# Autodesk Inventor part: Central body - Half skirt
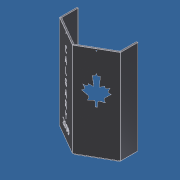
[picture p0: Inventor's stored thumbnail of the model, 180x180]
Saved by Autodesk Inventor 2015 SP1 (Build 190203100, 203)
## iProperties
Category: Mechanical Engineering Drawing and Design - CADD
Manager: Fábio Ricardo de Oliveira Souza
Company: SENAI - Serviço Nacional de Aprendizagem Industrial
Created: 2011-06
Part Number: Central body - Half skirt
Material: Steel
Description: Stainless Steel (DIN- X6NiCrTi18-10)
Document SubType Name: Sheet Metal
Designer: Guilherme Augusto Franco de Souza
Engineer: George Geraldo de Oliveia Silva
Authority: Fábio Ricardo de Oliveira Soza
Density: 7.85 g/cm^3
Sheet Metal Rule: Default_mm
Flat Pattern Width: 74.1468 cm
Flat Pattern Length: 67.5716 cm
Flat Pattern Area: 5010.21 cm^2
Sheet Metal Width: 741,468 mm
Sheet Metal Length: 675,716 mm
Sheet Metal Area: 501021,249 mm^2
Appearance: Machined 02
Subject: WorldSkill 2011 - London, England
Author: Guilherme Augusto Franco de Souza
Revision Number: 00
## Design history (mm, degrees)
sketch "Sketch1"
  geometry: L1 (0, -242.487)-(-210, -121.244); L2 (-210, -121.244)-(-210, 121.244); L3 (-210, 121.244)-(0, 242.487); L4 (0, 242.487)-(210, 121.244); L5 (210, 121.244)-(210, -121.244); L6 (210, -121.244)-(0, -242.487); 2 further points
  constraints: 12 end point, 1 coincident, 1 vertical alignment, 13 other
  dimensions: "d0" = 420 distance between parallel lines of L5 L2
extrude_surface "ExtrusionSrf1" sketch "Sketch1" dims "d1" = 648, "d2" = 0
feature "Trim1"
fillet "Fillet1" dims "d3" = 1.5 (computed from Thickness)
thicken "Thicken1" dims "d4" = 1.2 (= Thickness)
node "Flange1"
node "Flange2"
node "Flange4"
sketch "Sketch6"
  geometry: L1 (0.346, 645.6)-(240.409, 645.6) reference; 2 further points
  constraints: 1 vertical alignment
  dimensions: "d45" = 13 distance from line of L1 point (120.378, 632.6)
hole "Hole1" sketch "Sketch6" at (120.378, 632.6) diameter "d46" = 6.6; stored, may be unused: countersink angle "d50" = 90 deg, drill point angle "d52" = 118 deg; dims "d47" = 6, "d48" = 18, "d49" = 4.8, "d51" = 1.2 (= Thickness)
mirror "Mirror1"
sketch "Sketch7"
  geometry: L1 (6.755, -12.4)-(234, -12.4) reference; 2 further points
  constraints: 1 vertical alignment, 1 other
  dimensions: "d54" = 70 distance from line of L1 point (120.378, 57.6)
emboss "Emboss1" sketch "Sketch7" dims "d6" = 0.6 (= BendReliefDepth), "d55" = 1.2 (= Thickness), "d56" = 0
sketch "Sketch8"
  geometry: L1 (120.378, 297.6)-(126.378, 297.6); L2 (126.378, 297.6)-(126.378, 337.6); L3 (126.378, 337.6)-(165.378, 330.723); L4 (165.378, 330.723)-(156.696, 354.575); L5 (156.696, 354.575)-(195.378, 387.032); L6 (195.378, 387.032)-(175.594, 394.233); L7 (175.594, 394.233)-(189.086, 423.167); L8 (189.086, 423.167)-(160.152, 409.675); L9 (160.152, 409.675)-(161.987, 430.648); L10 (161.987, 430.648)-(136.003, 418.532); L11 (120.378, -144.039)-(120.378, 777.437) reference; L12 (189.086, 423.167)-(120.378, 354.459); L13 (175.594, 394.233)-(160.152, 409.675); L14 (136.003, 418.532)-(136.003, 433.532); L15 (136.003, 433.532)-(140.378, 483.532); L16 (140.378, 483.532)-(127.657, 477.6); L17 (127.657, 477.6)-(120.378, 497.6); L18 (120.378, 497.6)-(120.378, 297.6); L19 (6.755, -12.4)-(234, -12.4) reference; L20 (75.378, 330.723)-(84.059, 354.575); L21 (120.378, 297.6)-(114.378, 297.6); L22 (84.059, 354.575)-(45.378, 387.032); L23 (114.378, 297.6)-(114.378, 337.6); L24 (45.378, 387.032)-(65.161, 394.233); L25 (65.161, 394.233)-(80.603, 409.675); L26 (65.161, 394.233)-(51.669, 423.167); L27 (51.669, 423.167)-(120.378, 354.459); L28 (114.378, 337.6)-(75.378, 330.723); L29 (80.603, 409.675)-(78.768, 430.648); L30 (78.768, 430.648)-(104.752, 418.532); L31 (104.752, 418.532)-(104.752, 433.532); L32 (104.752, 433.532)-(100.378, 483.532); L33 (100.378, 483.532)-(113.098, 477.6); L34 (113.098, 477.6)-(120.378, 497.6); L35 (51.669, 423.167)-(80.603, 409.675); 1 further point
  constraints: 66 end point, 13 symmetric about line, 3 point on line, 2 equal length, 2 parallel, 1 collinear, 1 horizontal, 1 perpendicular, 1 vertical, 1 other
  dimensions: "d57" = 80 deg angle of L2 L3; "d58" = 60 deg angle of L3 L4; "d64" = 20 deg angle of L11 L17; "d65" = 20 vertical distance of L16.end L17.end; "d66" = 50 vertical distance of L14.end L15.end; "d67" = 15 distance of L10.end L14.end; "d68" = 60 deg angle of L16 L15; "d69" = 85 deg angle of L17 L16; "d70" = 40 deg angle of L8 L7; "d71" = 60 deg angle of L5 L6; "d72" = 60 deg angle of L10 L9; "d73" = 85 deg angle of L7 L6; "d74" = 30 distance from line of L7.end L13; "d75" = 45 deg angle of L18 L12; "d76" = 30 distance from line of L12 L5.end; "d77" = 20 distance from line of L11 L15.end; "d78" = 200 distance of L17.end L1.start; "d79" = 6 distance between parallel lines of L18 L2; "d80" = 40 distance of L1.end L2.end; "d81" = 75 distance from line of L18 L5.end; "d82" = 310 distance between parallel lines of L19 L1; "d83" = 45 distance from line of L18 L3.end
cut "Cut1" sketch "Sketch8" dims "d84" = 1.2 (= Thickness), "d85" = 0
feature "Corner Round1" dims "d86" = 10
node "Face1"
  sketch "Sketch9"
    geometry: L1 (133.918, 100.961)-(136.918, 100.961); L2 (136.918, 100.961)-(136.918, 52.552); L3 (136.918, 52.552)-(133.918, 52.552); L4 (133.918, 52.552)-(133.918, 100.961); L5 (103.902, 101.827)-(106.902, 101.827); L6 (106.902, 101.827)-(106.902, 53.418); L7 (106.902, 53.418)-(103.902, 53.418); L8 (103.902, 53.418)-(103.902, 101.827); L9 (112.679, 225.558)-(112.679, 210.517) reference; L10 (103.902, 219.538)-(138.933, 219.538); L11 (138.933, 219.538)-(138.933, 216.538); L12 (138.933, 216.538)-(103.902, 216.538); L13 (103.902, 216.538)-(103.902, 219.538); L14 (126.18, 271.741)-(119.989, 290.574) reference; L15 (119.989, 290.574)-(113.83, 271.741) reference; L16 (122.616, 282.582)-(123.553, 279.732); L17 (123.553, 279.732)-(145.154, 286.834); L18 (145.154, 286.834)-(144.217, 289.684); L19 (144.217, 289.684)-(122.616, 282.582); L20 (117.375, 282.583)-(116.443, 279.732); L21 (116.443, 279.732)-(99.552, 285.255); L22 (99.552, 285.255)-(100.484, 288.107); L23 (100.484, 288.107)-(117.375, 282.583); L24 (126.18, 469.318)-(119.989, 488.151) reference; L25 (119.989, 488.151)-(113.83, 469.318) reference; L26 (122.616, 480.159)-(123.553, 477.309); L27 (123.553, 477.309)-(139.447, 482.534); L28 (139.447, 482.534)-(138.51, 485.384); L29 (138.51, 485.384)-(122.616, 480.159); L30 (117.375, 480.16)-(116.443, 477.309); L31 (116.443, 477.309)-(102.535, 481.857); L32 (102.535, 481.857)-(103.467, 484.708); L33 (103.467, 484.708)-(117.375, 480.16); L34 (150.779, 86.944)-(182.005, 86.944); L35 (182.005, 86.944)-(182.005, 83.944); L36 (182.005, 83.944)-(150.779, 83.944); L37 (150.779, 83.944)-(150.779, 86.944); 13 further points
    constraints: 64 end point, 16 parallel, 13 midpoint, 8 perpendicular, 7 equal length, 4 collinear, 4 horizontal, 2 horizontal alignment, 2 vertical alignment
    dimensions: "d87" = 3 distance between parallel lines of L8 L6
body "Solid1"
body "Srf1"
sketch "Sketch2"
  geometry: L1 through (0, 60.189) direction (0, -1); L2 through (6, 0) direction (1, 0); L3 (12, 0)-(12, 120.378); L4 (12, 120.378)-(0, 120.378)
  constraints: 6 end point, 1 horizontal, 1 perpendicular, 1 vertical
face "Plate1" dims "d5" = 1.2 (= BendReliefWidth), "d6" = 0.6 (= BendReliefDepth), "d7" = 2.4 (= MinimumRemnant), "d8" = 1.2 (= BendRadius), "d9" = 12, "d10" = 90 deg, "d11" = 1.2 (= BendRadius), "d12" = 4.8 (= CornerReliefSize), "d13" = 0.6 (= 0.5 x GapSize), "d14" = 1.2 (= JacobiRadiusSize), "SeamGap" = 0.01, "Thickness" = 1.2 (derived)
bend "Bend1" dims "d5" = 1.2 (= BendReliefWidth), "d6" = 0.6 (= BendReliefDepth), "d7" = 2.4 (= MinimumRemnant), "d8" = 1.2 (= BendRadius), "d9" = 12, "d10" = 90 deg, "d11" = 1.2 (= BendRadius), "SeamGap" = 0.01, "Thickness" = 1.2 (derived)
feature "Corner1" dims "d9" = 12, "d10" = 90 deg, "d12" = 4.8 (= CornerReliefSize), "d13" = 0.6 (= 0.5 x GapSize), "d14" = 1.2 (= JacobiRadiusSize)
sketch "Sketch3"
  geometry: L1 through (-104.25, 60.189) direction (0.866, -0.5); L2 through (2.5, 4.33) direction (0.5, 0.866); L3 (5, 8.66)-(-203.5, 129.038); L4 (-203.5, 129.038)-(-208.5, 120.378)
  constraints: 6 end point, 1 perpendicular, 2 other
face "Plate2" dims "d15" = 1.2 (= BendReliefWidth), "d16" = 0.6 (= BendReliefDepth), "d17" = 2.4 (= MinimumRemnant), "d18" = 1.2 (= BendRadius), "d19" = 10, "d20" = 90 deg, "d21" = 0.3 (= 0.25 x BendRadius), "d22" = 4.8 (= CornerReliefSize), "d23" = 0.6 (= 0.5 x GapSize), "d24" = 1.2 (= JacobiRadiusSize), "SeamGap" = 0.01, "Thickness" = 1.2 (derived)
bend "Bend2" dims "d15" = 1.2 (= BendReliefWidth), "d16" = 0.6 (= BendReliefDepth), "d17" = 2.4 (= MinimumRemnant), "d18" = 1.2 (= BendRadius), "d19" = 10, "d20" = 90 deg, "d21" = 0.3 (= 0.25 x BendRadius), "SeamGap" = 0.01, "Thickness" = 1.2 (derived)
feature "Corner2" dims "d19" = 10, "d20" = 90 deg, "d22" = 4.8 (= CornerReliefSize), "d23" = 0.6 (= 0.5 x GapSize), "d24" = 1.2 (= JacobiRadiusSize)
sketch "Sketch5"
  geometry: L1 through (56.984, 0) direction (-1, 2.8e-31); L2 through (0, -5.6) direction (7.64e-30, -1); L3 (0, -11.2)-(113.969, -11.2); L4 (113.969, -11.2)-(113.969, 0)
  constraints: 6 end point, 1 horizontal, 1 perpendicular, 1 vertical
face "Plate4" dims "d35" = 1.2 (= BendReliefWidth), "d36" = 0.6 (= BendReliefDepth), "d37" = 2.4 (= MinimumRemnant), "d38" = 1.2 (= BendRadius), "d39" = 11.2 (computed from Thickness), "d40" = 90 deg, "d41" = 0.3 (derived), "d42" = 4.8 (= CornerReliefSize), "d43" = 1.2 (= GapSize), "d44" = 1.2 (= JacobiRadiusSize), "SeamGap" = 0.01, "Thickness" = 1.2 (derived)
bend "Bend4" dims "d35" = 1.2 (= BendReliefWidth), "d36" = 0.6 (= BendReliefDepth), "d37" = 2.4 (= MinimumRemnant), "d38" = 1.2 (= BendRadius), "d39" = 11.2 (computed from Thickness), "d40" = 90 deg, "d41" = 0.3 (derived), "SeamGap" = 0.01, "Thickness" = 1.2 (derived)
feature "Corner4" dims "d39" = 11.2 (computed from Thickness), "d40" = 90 deg, "d42" = 4.8 (= CornerReliefSize), "d43" = 1.2 (= GapSize), "d44" = 1.2 (= JacobiRadiusSize)
face "Plate5" dims "d88" = 1.2 (= BendRadius), "d89" = 1.2 (= BendReliefWidth), "d91" = 2.4 (= MinimumRemnant), "Thickness" = 1.2 (derived)
bend "Bend5" dims "d88" = 1.2 (= BendRadius), "d89" = 1.2 (= BendReliefWidth), "d90" = 0.6 (= BendReliefDepth), "d91" = 2.4 (= MinimumRemnant), "d92" = 1.2 (= BendRadius), "SeamGap" = 0.01, "Thickness" = 1.2 (derived)
feature "Definition1"
other parameters: "BendRadius" = 1.2 (= Thickness), "BendReliefWidth" = 1.2 (= Thickness), "BendReliefDepth" = 0.6 (= 0.5 x Thickness), "CornerReliefSize" = 4.8 (= 4 x Thickness), "MinimumRemnant" = 2.4 (= 2 x Thickness), "TransitionRadius" = 1.2 (= BendRadius), "JacobiRadiusSize" = 1.2 (= BendRadius), "GapSize" = 1.2 (= Thickness), "BendRadius" = 1.2, "BendReliefDepth" = 0.6, "BendReliefWidth" = 1.2, "CornerReliefSize" = 4.8, "GapSize" = 1.2, "JacobiRadiusSize" = 1.2, "MinimumRemnant" = 2.4, "Thickness" = 1.2, "TransitionRadius" = 1.2
